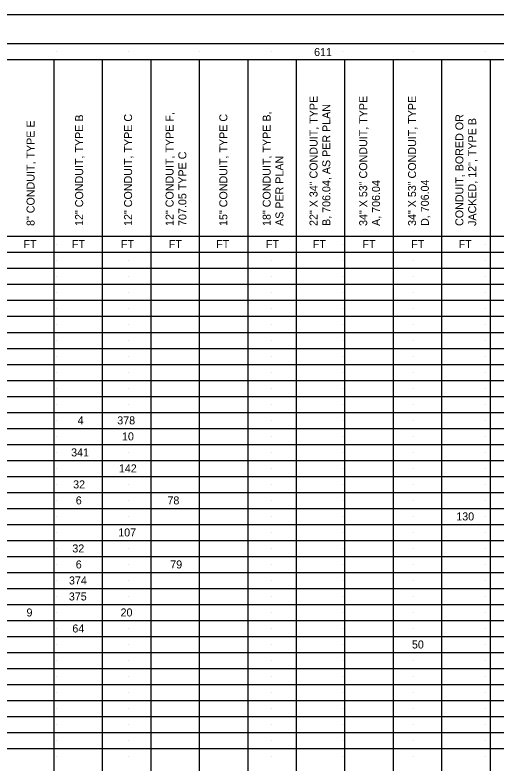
# Model space of a CAD drawing. Extents: x 2073163.9 to 2073197.9, y 634076.5 to 634098.5.
# Drawn here: x 2073180.84 to 2073189.26, y 634085.46 to 634098.55 of the extents above; entities that cross this region are included whole.
import ezdxf

# ---------------------------------------------------------------- set-up
doc = ezdxf.new("R2010")
doc.units = 0
for name, color, linetype in [('SH_Border', 7, 'Continuous'), ('SH_Cut_Line', 7, 'Continuous'), ('SH_Data', 7, 'Continuous'), ('SH_Text', 7, 'Continuous')]:
    doc.layers.add(name, color=color, linetype=linetype)

msp = doc.modelspace()

# ---------------------------------------------------------------- linework, layer by layer
at = {"layer": 'SH_Border'}
msp.add_lwpolyline([(2073165.446, 634098.05), (2073197.446, 634098.05), (2073197.446, 634077.05), (2073165.446, 634077.05)], close=True, dxfattribs=at)
at = {"layer": 'SH_Cut_Line'}
msp.add_lwpolyline([(2073163.946, 634076.55), (2073197.946, 634076.55), (2073197.946, 634098.55), (2073163.946, 634098.55)], close=True, dxfattribs=at)
at = {"layer": 'SH_Data'}
for p, q in [((2073181.571, 634097.91), (2073181.571, 634097.91)), ((2073181.571, 634097.91), (2073181.571, 634097.91)), ((2073182.821, 634097.91), (2073182.821, 634097.91)), ((2073182.821, 634097.91), (2073182.821, 634097.91)), ((2073182.821, 634097.91), (2073182.821, 634097.91)), ((2073184.071, 634097.91), (2073184.071, 634097.91)), ((2073184.071, 634097.91), (2073184.071, 634097.91)), ((2073184.071, 634097.91), (2073184.071, 634097.91)), ((2073184.071, 634097.91), (2073184.071, 634097.91)), ((2073185.321, 634097.91), (2073185.321, 634097.91)), ((2073185.321, 634097.91), (2073185.321, 634097.91)), ((2073185.321, 634097.91), (2073185.321, 634097.91)), ((2073185.321, 634097.91), (2073185.321, 634097.91)), ((2073185.321, 634097.91), (2073185.321, 634097.91)), ((2073186.571, 634097.91), (2073186.571, 634097.91)), ((2073187.821, 634097.91), (2073187.821, 634097.91)), ((2073189.071, 634097.91), (2073189.071, 634097.91)), ((2073171.345, 634097.77), (2073195.946, 634097.77)), ((2073171.345, 634094.682), (2073195.945, 634094.682)), ((2073181.571, 634094.538), (2073181.571, 634094.538)), ((2073181.571, 634094.538), (2073181.571, 634094.538)), ((2073182.821, 634094.538), (2073182.821, 634094.538)), ((2073182.821, 634094.538), (2073182.821, 634094.538)), ((2073182.821, 634094.538), (2073182.821, 634094.538)), ((2073184.071, 634094.538), (2073184.071, 634094.538)), ((2073184.071, 634094.538), (2073184.071, 634094.538)), ((2073184.071, 634094.538), (2073184.071, 634094.538)), ((2073184.071, 634094.538), (2073184.071, 634094.538)), ((2073185.321, 634094.538), (2073185.321, 634094.538)), ((2073185.321, 634094.538), (2073185.321, 634094.538)), ((2073185.321, 634094.538), (2073185.321, 634094.538)), ((2073185.321, 634094.538), (2073185.321, 634094.538)), ((2073185.321, 634094.538), (2073185.321, 634094.538)), ((2073186.571, 634094.538), (2073186.571, 634094.538)), ((2073187.821, 634094.538), (2073187.821, 634094.538)), ((2073189.071, 634094.538), (2073189.071, 634094.538)), ((2073165.446, 634094.398), (2073195.946, 634094.398)), ((2073181.571, 634094.258), (2073181.571, 634094.258)), ((2073182.821, 634094.258), (2073182.821, 634094.258)), ((2073184.071, 634094.258), (2073184.071, 634094.258)), ((2073185.321, 634094.258), (2073185.321, 634094.258)), ((2073186.571, 634094.258), (2073186.571, 634094.258)), ((2073187.821, 634094.258), (2073187.821, 634094.258)), ((2073189.071, 634094.258), (2073189.071, 634094.258)), ((2073165.44, 634094.118), (2073195.948, 634094.118)), ((2073181.571, 634093.978), (2073181.571, 634093.978)), ((2073182.821, 634093.978), (2073182.821, 634093.978)), ((2073184.071, 634093.978), (2073184.071, 634093.978)), ((2073185.321, 634093.978), (2073185.321, 634093.978)), ((2073186.571, 634093.978), (2073186.571, 634093.978)), ((2073187.821, 634093.978), (2073187.821, 634093.978)), ((2073189.071, 634093.978), (2073189.071, 634093.978)), ((2073165.45, 634093.838), (2073195.947, 634093.838)), ((2073181.571, 634093.698), (2073181.571, 634093.698)), ((2073182.821, 634093.698), (2073182.821, 634093.698)), ((2073184.071, 634093.698), (2073184.071, 634093.698)), ((2073185.321, 634093.698), (2073185.321, 634093.698)), ((2073186.571, 634093.698), (2073186.571, 634093.698)), ((2073187.821, 634093.698), (2073187.821, 634093.698)), ((2073189.071, 634093.698), (2073189.071, 634093.698)), ((2073165.45, 634093.558), (2073195.947, 634093.558)), ((2073181.571, 634093.418), (2073181.571, 634093.418)), ((2073182.821, 634093.418), (2073182.821, 634093.418)), ((2073184.071, 634093.418), (2073184.071, 634093.418)), ((2073185.321, 634093.418), (2073185.321, 634093.418)), ((2073186.571, 634093.418), (2073186.571, 634093.418)), ((2073187.821, 634093.418), (2073187.821, 634093.418)), ((2073189.071, 634093.418), (2073189.071, 634093.418)), ((2073165.447, 634093.278), (2073195.949, 634093.278)), ((2073181.571, 634093.138), (2073181.571, 634093.138)), ((2073182.821, 634093.138), (2073182.821, 634093.138)), ((2073184.071, 634093.138), (2073184.071, 634093.138)), ((2073185.321, 634093.138), (2073185.321, 634093.138)), ((2073186.571, 634093.138), (2073186.571, 634093.138)), ((2073187.821, 634093.138), (2073187.821, 634093.138)), ((2073189.071, 634093.138), (2073189.071, 634093.138)), ((2073165.444, 634092.998), (2073195.947, 634092.998)), ((2073181.571, 634092.858), (2073181.571, 634092.858)), ((2073182.821, 634092.858), (2073182.821, 634092.858)), ((2073184.071, 634092.858), (2073184.071, 634092.858)), ((2073185.321, 634092.858), (2073185.321, 634092.858)), ((2073186.571, 634092.858), (2073186.571, 634092.858)), ((2073187.821, 634092.858), (2073187.821, 634092.858)), ((2073189.071, 634092.858), (2073189.071, 634092.858)), ((2073165.454, 634092.718), (2073195.947, 634092.718)), ((2073181.571, 634092.578), (2073181.571, 634092.578)), ((2073182.821, 634092.578), (2073182.821, 634092.578)), ((2073184.071, 634092.578), (2073184.071, 634092.578)), ((2073185.321, 634092.578), (2073185.321, 634092.578)), ((2073186.571, 634092.578), (2073186.571, 634092.578)), ((2073187.821, 634092.578), (2073187.821, 634092.578)), ((2073189.071, 634092.578), (2073189.071, 634092.578)), ((2073165.45, 634092.438), (2073195.943, 634092.438)), ((2073181.571, 634092.298), (2073181.571, 634092.298)), ((2073182.821, 634092.298), (2073182.821, 634092.298)), ((2073184.071, 634092.298), (2073184.071, 634092.298)), ((2073185.321, 634092.298), (2073185.321, 634092.298)), ((2073186.571, 634092.298), (2073186.571, 634092.298)), ((2073187.821, 634092.298), (2073187.821, 634092.298)), ((2073189.071, 634092.298), (2073189.071, 634092.298)), ((2073165.448, 634092.158), (2073195.943, 634092.158)), ((2073181.571, 634092.018), (2073181.571, 634092.018)), ((2073182.821, 634092.018), (2073182.821, 634092.018)), ((2073184.071, 634092.018), (2073184.071, 634092.018)), ((2073185.321, 634092.018), (2073185.321, 634092.018)), ((2073186.571, 634092.018), (2073186.571, 634092.018)), ((2073187.821, 634092.018), (2073187.821, 634092.018)), ((2073189.071, 634092.018), (2073189.071, 634092.018)), ((2073165.448, 634091.878), (2073195.943, 634091.878)), ((2073181.571, 634091.738), (2073181.571, 634091.738)), ((2073182.821, 634091.738), (2073182.821, 634091.738)), ((2073184.071, 634091.738), (2073184.071, 634091.738)), ((2073185.321, 634091.738), (2073185.321, 634091.738)), ((2073186.571, 634091.738), (2073186.571, 634091.738)), ((2073187.821, 634091.738), (2073187.821, 634091.738)), ((2073189.071, 634091.738), (2073189.071, 634091.738)), ((2073165.448, 634091.598), (2073195.948, 634091.598)), ((2073181.571, 634091.458), (2073181.571, 634091.458)), ((2073182.821, 634091.458), (2073182.821, 634091.458)), ((2073184.071, 634091.458), (2073184.071, 634091.458)), ((2073185.321, 634091.458), (2073185.321, 634091.458)), ((2073186.571, 634091.458), (2073186.571, 634091.458)), ((2073187.821, 634091.458), (2073187.821, 634091.458)), ((2073189.071, 634091.458), (2073189.071, 634091.458)), ((2073165.451, 634091.318), (2073195.939, 634091.318)), ((2073165.451, 634091.318), (2073195.944, 634091.318)), ((2073181.571, 634091.178), (2073181.571, 634091.178)), ((2073182.821, 634091.178), (2073182.821, 634091.178)), ((2073184.071, 634091.178), (2073184.071, 634091.178)), ((2073185.321, 634091.178), (2073185.321, 634091.178)), ((2073186.571, 634091.178), (2073186.571, 634091.178)), ((2073187.821, 634091.178), (2073187.821, 634091.178)), ((2073189.071, 634091.178), (2073189.071, 634091.178)), ((2073165.448, 634091.038), (2073195.944, 634091.038)), ((2073181.571, 634090.898), (2073181.571, 634090.898)), ((2073182.821, 634090.898), (2073182.821, 634090.898)), ((2073184.071, 634090.898), (2073184.071, 634090.898)), ((2073185.321, 634090.898), (2073185.321, 634090.898)), ((2073186.571, 634090.898), (2073186.571, 634090.898)), ((2073187.821, 634090.898), (2073187.821, 634090.898)), ((2073189.071, 634090.898), (2073189.071, 634090.898)), ((2073165.445, 634090.758), (2073195.942, 634090.758)), ((2073181.571, 634090.618), (2073181.571, 634090.618)), ((2073182.821, 634090.618), (2073182.821, 634090.618)), ((2073184.071, 634090.618), (2073184.071, 634090.618)), ((2073185.321, 634090.618), (2073185.321, 634090.618)), ((2073186.571, 634090.618), (2073186.571, 634090.618)), ((2073187.821, 634090.618), (2073187.821, 634090.618)), ((2073189.071, 634090.618), (2073189.071, 634090.618)), ((2073165.442, 634090.478), (2073195.946, 634090.478)), ((2073181.571, 634090.338), (2073181.571, 634090.338)), ((2073182.821, 634090.338), (2073182.821, 634090.338)), ((2073184.071, 634090.338), (2073184.071, 634090.338)), ((2073185.321, 634090.338), (2073185.321, 634090.338)), ((2073186.571, 634090.338), (2073186.571, 634090.338)), ((2073187.821, 634090.338), (2073187.821, 634090.338)), ((2073189.071, 634090.338), (2073189.071, 634090.338)), ((2073165.442, 634090.198), (2073195.946, 634090.198)), ((2073181.571, 634090.058), (2073181.571, 634090.058)), ((2073182.821, 634090.058), (2073182.821, 634090.058)), ((2073184.071, 634090.058), (2073184.071, 634090.058)), ((2073185.321, 634090.058), (2073185.321, 634090.058)), ((2073186.571, 634090.058), (2073186.571, 634090.058)), ((2073187.821, 634090.058), (2073187.821, 634090.058)), ((2073189.071, 634090.058), (2073189.071, 634090.058)), ((2073165.446, 634089.918), (2073195.946, 634089.918)), ((2073181.571, 634089.778), (2073181.571, 634089.778)), ((2073182.821, 634089.778), (2073182.821, 634089.778)), ((2073184.071, 634089.778), (2073184.071, 634089.778)), ((2073185.321, 634089.778), (2073185.321, 634089.778)), ((2073186.571, 634089.778), (2073186.571, 634089.778)), ((2073187.821, 634089.778), (2073187.821, 634089.778)), ((2073189.071, 634089.778), (2073189.071, 634089.778)), ((2073165.446, 634089.638), (2073195.946, 634089.638)), ((2073181.571, 634089.498), (2073181.571, 634089.498)), ((2073182.821, 634089.498), (2073182.821, 634089.498)), ((2073184.071, 634089.498), (2073184.071, 634089.498)), ((2073185.321, 634089.498), (2073185.321, 634089.498)), ((2073186.571, 634089.498), (2073186.571, 634089.498)), ((2073187.821, 634089.498), (2073187.821, 634089.498)), ((2073189.071, 634089.498), (2073189.071, 634089.498)), ((2073165.446, 634089.358), (2073195.946, 634089.358)), ((2073181.571, 634089.218), (2073181.571, 634089.218)), ((2073182.821, 634089.218), (2073182.821, 634089.218)), ((2073184.071, 634089.218), (2073184.071, 634089.218)), ((2073185.321, 634089.218), (2073185.321, 634089.218)), ((2073186.571, 634089.218), (2073186.571, 634089.218)), ((2073187.821, 634089.218), (2073187.821, 634089.218)), ((2073189.071, 634089.218), (2073189.071, 634089.218)), ((2073165.446, 634089.078), (2073195.946, 634089.078)), ((2073181.571, 634088.938), (2073181.571, 634088.938)), ((2073182.821, 634088.938), (2073182.821, 634088.938)), ((2073184.071, 634088.938), (2073184.071, 634088.938)), ((2073185.321, 634088.938), (2073185.321, 634088.938)), ((2073186.571, 634088.938), (2073186.571, 634088.938)), ((2073187.821, 634088.938), (2073187.821, 634088.938)), ((2073189.071, 634088.938), (2073189.071, 634088.938)), ((2073165.446, 634088.798), (2073195.946, 634088.798)), ((2073181.571, 634088.658), (2073181.571, 634088.658)), ((2073182.821, 634088.658), (2073182.821, 634088.658)), ((2073184.071, 634088.658), (2073184.071, 634088.658)), ((2073185.321, 634088.658), (2073185.321, 634088.658)), ((2073186.571, 634088.658), (2073186.571, 634088.658)), ((2073187.821, 634088.658), (2073187.821, 634088.658)), ((2073189.071, 634088.658), (2073189.071, 634088.658)), ((2073165.446, 634088.518), (2073195.946, 634088.518)), ((2073181.571, 634088.378), (2073181.571, 634088.378)), ((2073182.821, 634088.378), (2073182.821, 634088.378)), ((2073184.071, 634088.378), (2073184.071, 634088.378)), ((2073185.321, 634088.378), (2073185.321, 634088.378)), ((2073186.571, 634088.378), (2073186.571, 634088.378)), ((2073187.821, 634088.378), (2073187.821, 634088.378)), ((2073189.071, 634088.378), (2073189.071, 634088.378)), ((2073165.446, 634088.238), (2073195.946, 634088.238)), ((2073181.571, 634088.098), (2073181.571, 634088.098)), ((2073182.821, 634088.098), (2073182.821, 634088.098)), ((2073184.071, 634088.098), (2073184.071, 634088.098)), ((2073185.321, 634088.098), (2073185.321, 634088.098)), ((2073186.571, 634088.098), (2073186.571, 634088.098)), ((2073187.821, 634088.098), (2073187.821, 634088.098)), ((2073189.071, 634088.098), (2073189.071, 634088.098)), ((2073165.446, 634087.958), (2073195.946, 634087.958)), ((2073181.571, 634087.818), (2073181.571, 634087.818)), ((2073182.821, 634087.818), (2073182.821, 634087.818)), ((2073184.071, 634087.818), (2073184.071, 634087.818)), ((2073185.321, 634087.818), (2073185.321, 634087.818)), ((2073186.571, 634087.818), (2073186.571, 634087.818)), ((2073187.821, 634087.818), (2073187.821, 634087.818)), ((2073189.071, 634087.818), (2073189.071, 634087.818)), ((2073165.446, 634087.678), (2073195.946, 634087.678)), ((2073181.571, 634087.538), (2073181.571, 634087.538)), ((2073182.821, 634087.538), (2073182.821, 634087.538)), ((2073184.071, 634087.538), (2073184.071, 634087.538)), ((2073185.321, 634087.538), (2073185.321, 634087.538)), ((2073186.571, 634087.538), (2073186.571, 634087.538)), ((2073187.821, 634087.538), (2073187.821, 634087.538)), ((2073189.071, 634087.538), (2073189.071, 634087.538)), ((2073165.446, 634087.398), (2073195.946, 634087.398)), ((2073181.571, 634087.258), (2073181.571, 634087.258)), ((2073182.821, 634087.258), (2073182.821, 634087.258)), ((2073184.071, 634087.258), (2073184.071, 634087.258)), ((2073185.321, 634087.258), (2073185.321, 634087.258)), ((2073186.571, 634087.258), (2073186.571, 634087.258)), ((2073187.821, 634087.258), (2073187.821, 634087.258)), ((2073189.071, 634087.258), (2073189.071, 634087.258)), ((2073165.446, 634087.118), (2073195.946, 634087.118)), ((2073181.571, 634086.978), (2073181.571, 634086.978)), ((2073182.821, 634086.978), (2073182.821, 634086.978)), ((2073184.071, 634086.978), (2073184.071, 634086.978)), ((2073185.321, 634086.978), (2073185.321, 634086.978)), ((2073186.571, 634086.978), (2073186.571, 634086.978)), ((2073187.821, 634086.978), (2073187.821, 634086.978)), ((2073189.071, 634086.978), (2073189.071, 634086.978)), ((2073165.446, 634086.838), (2073195.946, 634086.838)), ((2073181.571, 634086.698), (2073181.571, 634086.698)), ((2073182.821, 634086.698), (2073182.821, 634086.698)), ((2073184.071, 634086.698), (2073184.071, 634086.698)), ((2073185.321, 634086.698), (2073185.321, 634086.698)), ((2073186.571, 634086.698), (2073186.571, 634086.698)), ((2073187.821, 634086.698), (2073187.821, 634086.698)), ((2073189.071, 634086.698), (2073189.071, 634086.698)), ((2073165.446, 634086.558), (2073195.946, 634086.558)), ((2073181.571, 634086.418), (2073181.571, 634086.418)), ((2073182.821, 634086.418), (2073182.821, 634086.418)), ((2073184.071, 634086.418), (2073184.071, 634086.418)), ((2073185.321, 634086.418), (2073185.321, 634086.418)), ((2073186.571, 634086.418), (2073186.571, 634086.418)), ((2073187.821, 634086.418), (2073187.821, 634086.418)), ((2073189.071, 634086.418), (2073189.071, 634086.418)), ((2073165.446, 634086.278), (2073195.946, 634086.278)), ((2073181.571, 634086.138), (2073181.571, 634086.138)), ((2073182.821, 634086.138), (2073182.821, 634086.138)), ((2073184.071, 634086.138), (2073184.071, 634086.138)), ((2073185.321, 634086.138), (2073185.321, 634086.138)), ((2073186.571, 634086.138), (2073186.571, 634086.138)), ((2073187.821, 634086.138), (2073187.821, 634086.138)), ((2073189.071, 634086.138), (2073189.071, 634086.138)), ((2073165.446, 634085.998), (2073195.946, 634085.998)), ((2073181.571, 634085.858), (2073181.571, 634085.858)), ((2073182.821, 634085.858), (2073182.821, 634085.858)), ((2073184.071, 634085.858), (2073184.071, 634085.858)), ((2073185.321, 634085.858), (2073185.321, 634085.858)), ((2073186.571, 634085.858), (2073186.571, 634085.858)), ((2073187.821, 634085.858), (2073187.821, 634085.858)), ((2073189.071, 634085.858), (2073189.071, 634085.858)), ((2073165.446, 634085.718), (2073195.946, 634085.718)), ((2073181.571, 634085.578), (2073181.571, 634085.578)), ((2073182.821, 634085.578), (2073182.821, 634085.578)), ((2073184.071, 634085.578), (2073184.071, 634085.578)), ((2073185.321, 634085.578), (2073185.321, 634085.578)), ((2073186.571, 634085.578), (2073186.571, 634085.578)), ((2073187.821, 634085.578), (2073187.821, 634085.578)), ((2073189.071, 634085.578), (2073189.071, 634085.578))]:
    msp.add_line(p, q, dxfattribs=at)
at = {"layer": 'SH_Text'}
for p, q in [((2073181.525, 634077.05), (2073181.525, 634097.77)), ((2073182.373, 634077.05), (2073182.373, 634097.77)), ((2073183.221, 634077.05), (2073183.221, 634097.77)), ((2073184.069, 634077.05), (2073184.069, 634097.77)), ((2073184.918, 634077.05), (2073184.918, 634097.77)), ((2073185.766, 634077.05), (2073185.766, 634097.77)), ((2073186.614, 634077.05), (2073186.614, 634097.77)), ((2073187.463, 634077.05), (2073187.463, 634097.77)), ((2073188.311, 634077.05), (2073188.311, 634097.77)), ((2073189.159, 634077.05), (2073189.159, 634097.77))]:
    msp.add_line(p, q, dxfattribs=at)

# ---------------------------------------------------------------- texts
for s, rotation, p in [('611', 0.0001, (2073186.074, 634097.831)), ('22" X 34" CONDUIT, TYPE', 90.0001, (2073186.134, 634094.859)), ('34" X 53" CONDUIT, TYPE', 90.0001, (2073187.003, 634094.859)), ('34" X 53" CONDUIT, TYPE', 90.0001, (2073187.858, 634094.859)), ('B, 706.04, AS PER PLAN', 90.0001, (2073186.358, 634094.859)), ('12" CONDUIT, TYPE B', 90.0001, (2073182.033, 634094.859)), ('12" CONDUIT, TYPE C', 90.0001, (2073182.889, 634094.859)), ('12" CONDUIT, TYPE F,', 90.0001, (2073183.615, 634094.859)), ('15" CONDUIT, TYPE C', 90.0001, (2073184.556, 634094.859)), ('18" CONDUIT, TYPE B,', 90.0001, (2073185.314, 634094.859)), ('CONDUIT, BORED OR', 90.0001, (2073188.686, 634094.859)), ('JACKED, 12", TYPE B', 90.0001, (2073188.91, 634094.859)), ('8" CONDUIT, TYPE E', 90.0001, (2073181.183, 634094.859)), ('707.05 TYPE C', 90.0001, (2073183.839, 634094.859)), ('AS PER PLAN', 90.0001, (2073185.538, 634094.859)), ('A, 706.04', 90.0001, (2073187.227, 634094.859)), ('D, 706.04', 90.0001, (2073188.082, 634094.859)), ('FT', 0.0001, (2073180.988, 634094.472)), ('FT', 0.0001, (2073181.837, 634094.472)), ('FT', 0.0001, (2073182.694, 634094.472)), ('FT', 0.0001, (2073183.531, 634094.472)), ('FT', 0.0001, (2073184.361, 634094.472)), ('FT', 0.0001, (2073185.231, 634094.472)), ('FT', 0.0001, (2073186.051, 634094.472)), ('FT', 0.0001, (2073186.92, 634094.472)), ('FT', 0.0001, (2073187.774, 634094.472)), ('FT', 0.0001, (2073188.603, 634094.472)), ('4', 0.0001, (2073181.936, 634091.388)), ('378', 0.0001, (2073182.63, 634091.388)), ('10', 0.0001, (2073182.713, 634091.108)), ('341', 0.0001, (2073181.823, 634090.828)), ('142', 0.0001, (2073182.658, 634090.548)), ('32', 0.0001, (2073181.858, 634090.268)), ('6', 0.0001, (2073181.904, 634089.988)), ('78', 0.0001, (2073183.508, 634089.988)), ('130', 0.0001, (2073188.562, 634089.708)), ('107', 0.0001, (2073182.647, 634089.428)), ('32', 0.0001, (2073181.844, 634089.148)), ('6', 0.0001, (2073181.904, 634088.868)), ('79', 0.0001, (2073183.557, 634088.868)), ('374', 0.0001, (2073181.785, 634088.588)), ('375', 0.0001, (2073181.783, 634088.308)), ('9', 0.0001, (2073181.042, 634088.028)), ('20', 0.0001, (2073182.688, 634088.028)), ('64', 0.0001, (2073181.844, 634087.748)), ('50', 0.0001, (2073187.786, 634087.468))]:
    msp.add_text(s, height=0.14, rotation=rotation, dxfattribs=at).set_placement(p)

doc.saveas('drawing.dxf')
